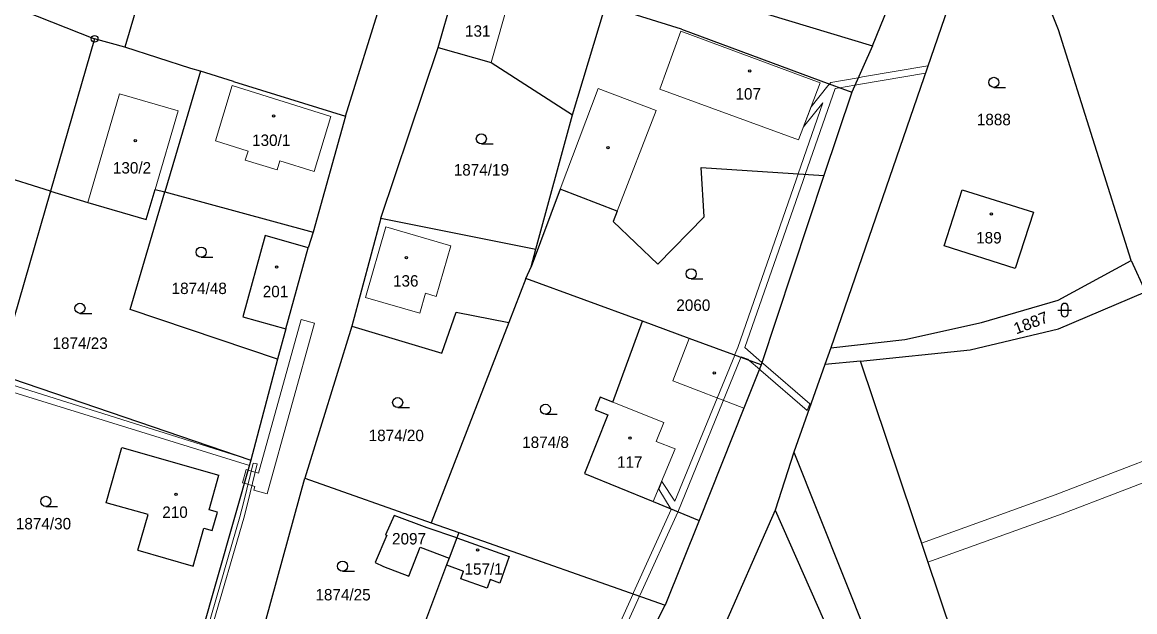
# Model space of a CAD drawing. Extents: x -820420 to -815896, y -1105820 to -1103643.
# Drawn here: x -818124.5 to -817959, y -1105443.7 to -1105356.1 of the extents above; entities that cross this region are included whole.
import ezdxf
from ezdxf.enums import TextEntityAlignment as Align

# ---------------------------------------------------------------- set-up
doc = ezdxf.new("R2010")
doc.units = 0
doc.header["$LTSCALE"] = 0.68
for name, color, linetype, lineweight in [('1', 7, 'Continuous', 25), ('13', 7, 'Continuous', 13), ('3', 7, 'Continuous', 25), ('4', 7, 'Continuous', 13), ('5', 7, 'Continuous', 25), ('8', 7, 'Continuous', 25)]:
    doc.layers.add(name, color=color, linetype=linetype, lineweight=lineweight)
doc.layers.add('2', color=7, linetype='Continuous')

msp = doc.modelspace()

# ---------------------------------------------------------------- linework, layer by layer
at = {"layer": '1'}
for p, q in [((-818102.39, -1105336.53), (-818109.27, -1105359.84)), ((-817970.34, -1105357.25), (-817977.63, -1105338.91)), ((-817982, -1105340.03), (-818004.22, -1105404.51)), ((-818076.41, -1105370.08), (-818069.32, -1105347.22)), ((-818062.64, -1105359.86), (-818059.62, -1105349.3)), ((-817998.02, -1105359.64), (-817994.74, -1105351.62)), ((-818124.41, -1105354.39), (-818113.75, -1105358.58)), ((-818042.65, -1105369.86), (-818037.9, -1105354.13)), ((-818026.42, -1105357.16), (-818034.57, -1105354.62)), ((-818013.64, -1105354.91), (-817998.02, -1105359.64)), ((-818026.42, -1105357.16), (-818005.71, -1105364.82)), ((-817959.52, -1105391.55), (-817970.34, -1105357.25)), ((-818113.75, -1105358.58), (-818120.31, -1105381.21)), ((-818109.27, -1105359.84), (-818113.75, -1105358.58)), ((-818099.42, -1105362.97), (-818109.27, -1105359.84)), ((-818071.19, -1105385.23), (-818062.64, -1105359.86)), ((-818062.64, -1105359.86), (-818054.77, -1105362.11)), ((-817998.02, -1105359.64), (-818001.1, -1105366.53)), ((-818054.77, -1105362.11), (-818042.65, -1105369.86)), ((-818098, -1105363.4), (-818099.88, -1105369.8)), ((-818098, -1105363.4), (-818099.42, -1105362.97)), ((-818093.1, -1105364.9), (-818098, -1105363.4)), ((-818093.1, -1105364.9), (-818076.41, -1105370.08)), ((-818005.71, -1105364.82), (-818001.1, -1105366.53)), ((-818001.1, -1105366.53), (-818005.25, -1105378.91)), ((-818099.88, -1105369.8), (-818103.3, -1105381.35)), ((-818076.41, -1105370.08), (-818081.24, -1105387.31)), ((-818048.09, -1105389.84), (-818042.65, -1105369.86)), ((-818120.31, -1105381.21), (-818129.72, -1105378.29)), ((-818023.51, -1105377.71), (-818005.25, -1105378.91)), ((-818023.06, -1105385.06), (-818023.51, -1105377.71)), ((-818005.25, -1105378.91), (-818014.59, -1105407.03)), ((-818120.31, -1105381.21), (-818128.21, -1105408.38)), ((-818120.31, -1105381.21), (-818114.77, -1105382.93)), ((-818108.46, -1105398.84), (-818103.3, -1105381.35)), ((-818106.07, -1105385.44), (-818104.72, -1105380.98)), ((-818104.72, -1105380.98), (-818103.3, -1105381.35)), ((-818103.3, -1105381.35), (-818081.24, -1105387.31)), ((-818044.47, -1105380.93), (-818048.81, -1105392.46)), ((-818036, -1105384.2), (-818044.47, -1105380.93)), ((-817987.33, -1105389.37), (-817984.69, -1105381.01)), ((-817984.69, -1105381.01), (-817974.04, -1105384.33)), ((-818114.77, -1105382.93), (-818106.07, -1105385.44)), ((-818036, -1105384.2), (-818036.59, -1105385.73)), ((-818071.19, -1105385.23), (-818075.5, -1105401.31)), ((-818071.19, -1105385.23), (-818048.09, -1105389.84)), ((-818036.59, -1105385.73), (-818029.95, -1105392.08)), ((-818029.95, -1105392.08), (-818023.06, -1105385.06)), ((-817974.04, -1105384.33), (-817976.78, -1105392.71)), ((-818081.24, -1105387.31), (-818081.98, -1105389.64)), ((-818088.36, -1105387.84), (-818091.72, -1105399.91)), ((-818081.98, -1105389.64), (-818088.36, -1105387.84)), ((-818085.32, -1105401.69), (-818081.98, -1105389.64)), ((-818048.81, -1105392.46), (-818048.09, -1105389.84)), ((-817976.78, -1105392.71), (-817987.33, -1105389.37)), ((-818049.58, -1105394.21), (-818048.81, -1105392.46)), ((-817970.41, -1105397.42), (-817959.52, -1105391.55)), ((-817959.52, -1105391.55), (-817957.4, -1105396.2)), ((-818049.58, -1105394.21), (-818052.13, -1105400.77)), ((-818032.25, -1105400.57), (-818049.58, -1105394.21)), ((-817981.82, -1105400.76), (-817970.41, -1105397.42)), ((-817970.34, -1105401.67), (-817957.4, -1105396.2)), ((-818086.54, -1105406.2), (-818108.46, -1105398.84)), ((-818091.72, -1105399.91), (-818085.32, -1105401.69)), ((-818052.13, -1105400.77), (-818063.69, -1105430.51)), ((-818062.07, -1105405.29), (-818059.98, -1105399.23)), ((-818059.98, -1105399.23), (-818052.13, -1105400.77)), ((-818036.66, -1105412.6), (-818032.25, -1105400.57)), ((-818025.31, -1105403.11), (-818032.25, -1105400.57)), ((-817993.22, -1105403.28), (-817981.82, -1105400.76)), ((-818085.32, -1105401.69), (-818086.54, -1105406.2)), ((-818075.5, -1105401.31), (-818082.49, -1105423.88)), ((-818075.5, -1105401.31), (-818062.07, -1105405.29)), ((-817983.48, -1105404.79), (-817970.34, -1105401.67)), ((-818014.59, -1105407.03), (-818025.31, -1105403.11)), ((-818004.22, -1105404.51), (-817993.22, -1105403.28)), ((-818004.22, -1105404.51), (-818005.1, -1105406.97)), ((-817999.82, -1105406.48), (-817983.48, -1105404.79)), ((-818086.54, -1105406.2), (-818090.49, -1105421.23)), ((-818014.59, -1105407.03), (-818017.16, -1105413.47)), ((-818005.1, -1105406.97), (-818009.73, -1105420.02)), ((-817999.82, -1105406.48), (-818005.1, -1105406.97)), ((-817981.08, -1105462.15), (-817999.82, -1105406.48)), ((-818128.21, -1105408.38), (-818090.49, -1105421.23)), ((-818038.53, -1105411.86), (-818039.28, -1105413.73)), ((-818036.66, -1105412.6), (-818038.53, -1105411.86)), ((-818039.28, -1105413.73), (-818037.4, -1105414.48)), ((-818017.16, -1105413.47), (-818023.81, -1105430.17)), ((-818037.4, -1105414.48), (-818040.86, -1105423.19)), ((-818112.05, -1105427.55), (-818109.69, -1105419.34)), ((-818109.69, -1105419.34), (-818095.28, -1105423.46)), ((-818009.73, -1105420.02), (-818012.52, -1105428.66)), ((-818009.73, -1105420.02), (-817994.18, -1105458.85)), ((-818090.49, -1105421.23), (-818099.7, -1105453.29)), ((-818096.73, -1105428.58), (-818095.28, -1105423.46)), ((-818088.22, -1105444.83), (-818082.49, -1105423.88)), ((-818082.49, -1105423.88), (-818063.69, -1105430.51)), ((-818040.86, -1105423.19), (-818030.63, -1105427.37)), ((-818105.78, -1105429.29), (-818112.05, -1105427.55)), ((-818095.46, -1105428.94), (-818096.73, -1105428.58)), ((-818030.63, -1105427.37), (-818023.81, -1105430.17)), ((-818012.52, -1105428.66), (-818024.71, -1105456.36)), ((-818012.52, -1105428.66), (-817998.06, -1105461.28)), ((-818107.3, -1105434.61), (-818105.78, -1105429.29)), ((-818096.24, -1105431.69), (-818095.46, -1105428.94)), ((-818069.16, -1105429.46), (-818070.49, -1105432.3)), ((-818064.28, -1105431.27), (-818069.16, -1105429.46)), ((-818063.69, -1105430.51), (-818059.58, -1105431.96)), ((-818023.81, -1105430.17), (-818028.84, -1105442.79)), ((-818099.11, -1105436.95), (-818097.51, -1105431.32)), ((-818097.51, -1105431.32), (-818096.24, -1105431.69)), ((-818059.88, -1105432.75), (-818064.28, -1105431.27)), ((-818059.58, -1105431.96), (-818059.88, -1105432.75)), ((-818059.58, -1105431.96), (-818028.84, -1105442.79)), ((-818070.26, -1105432.36), (-818072.03, -1105436.41)), ((-818070.49, -1105432.3), (-818070.26, -1105432.36)), ((-818059.88, -1105432.75), (-818061.01, -1105435.77)), ((-818059.88, -1105432.75), (-818052.05, -1105435.56)), ((-818107.3, -1105434.61), (-818099.11, -1105436.95)), ((-818067, -1105438.45), (-818065.32, -1105434.15)), ((-818065.32, -1105434.15), (-818061.01, -1105435.77)), ((-818072.03, -1105436.41), (-818070.79, -1105437.03)), ((-818070.79, -1105437.03), (-818067, -1105438.45)), ((-818061.39, -1105436.77), (-818067.26, -1105452.42)), ((-818061.01, -1105435.77), (-818061.39, -1105436.77)), ((-818061.39, -1105436.77), (-818058.88, -1105437.71)), ((-818052.05, -1105435.56), (-818053.46, -1105439.5)), ((-818059.28, -1105438.85), (-818058.88, -1105437.71)), ((-818055.37, -1105440.24), (-818059.28, -1105438.85)), ((-818054.92, -1105438.98), (-818055.37, -1105440.24)), ((-818053.46, -1105439.5), (-818054.92, -1105438.98)), ((-818039.13, -1105462.6), (-818028.84, -1105442.79))]:
    msp.add_line(p, q, dxfattribs=at)
at = {"layer": '13'}
for points in [[(-817989.77, -1105362.59), (-817999.5, -1105364.25), (-818000.13, -1105364.36), (-818000.62, -1105365.46), (-817999.81, -1105365.32), (-817990.15, -1105363.67)], [(-818000.13, -1105364.36), (-818004.22, -1105365.06), (-818004.42, -1105365.3), (-818002.93, -1105365.85), (-818000.62, -1105365.46)], [(-818002.93, -1105365.85), (-818004.42, -1105365.3), (-818004.65, -1105365.58), (-818007.12, -1105368.67), (-818008.26, -1105371.68), (-818005.38, -1105368.1), (-818009.06, -1105378.66), (-818009.37, -1105379.55), (-818018.05, -1105404.46), (-818018.49, -1105405.52), (-818018.52, -1105405.59), (-818017.58, -1105405.94), (-818017.54, -1105405.85), (-818016.57, -1105406.2), (-818016.36, -1105406.38), (-818014.59, -1105407.03), (-818014.48, -1105406.69), (-818017.01, -1105404.49), (-818008.33, -1105379.64), (-818008.01, -1105378.73), (-818003.56, -1105365.96)], [(-817906.26, -1105403.62), (-817870.42, -1105388.81), (-817857.72, -1105384.7), (-817855.6, -1105384.19), (-817850.44, -1105382.95), (-817847.44, -1105379.56), (-817849.48, -1105379.64), (-817852.45, -1105380.35), (-817858.54, -1105381.8), (-817871.44, -1105385.99), (-817907.52, -1105400.9), (-817913.62, -1105403.79), (-817946.01, -1105416.87), (-817970.85, -1105426.37), (-817990.71, -1105433.53), (-817989.76, -1105436.38), (-817969.79, -1105429.17), (-817944.93, -1105419.67), (-817912.4, -1105406.53)], [(-818083.03, -1105400.29), (-818089.38, -1105423.14), (-818090.91, -1105422.69), (-818091.47, -1105424.65), (-818089.92, -1105425.11), (-818090.07, -1105425.69), (-818088.09, -1105426.23), (-818081.05, -1105400.85)], [(-818032.68, -1105441.44), (-818032.59, -1105441.25), (-818027, -1105428.93), (-818017.58, -1105405.94), (-818018.52, -1105405.59), (-818027.44, -1105427.33), (-818029.34, -1105424.4), (-818029.81, -1105425.51), (-818027.95, -1105428.53), (-818033.55, -1105440.91), (-818033.64, -1105441.1)], [(-818016.36, -1105406.38), (-818014.85, -1105407.69), (-818014.59, -1105407.03)], [(-818014.48, -1105406.69), (-818014.59, -1105407.03), (-818014.85, -1105407.69), (-818014.62, -1105407.89), (-818007.75, -1105413.84), (-818007.36, -1105412.86), (-818014.23, -1105406.9)], [(-818128.53, -1105409.59), (-818128.79, -1105410.57), (-818127.23, -1105410.7), (-818090.71, -1105422), (-818090.49, -1105421.23), (-818127.03, -1105409.72)], [(-818109.75, -1105451.26), (-818104.73, -1105452.62), (-818100.81, -1105453.75), (-818099.35, -1105453.87), (-818098.43, -1105453.95), (-818097.44, -1105449.94), (-818096.34, -1105446.27), (-818091.57, -1105429.82), (-818090.96, -1105427.51), (-818089.57, -1105421.78), (-818090.15, -1105421.64), (-818091.54, -1105427.37), (-818092.15, -1105429.66), (-818096.92, -1105446.11), (-818098.02, -1105449.78), (-818098.89, -1105453.31), (-818099.7, -1105453.29), (-818100.71, -1105453.15), (-818104.57, -1105452.04), (-818110.17, -1105450.52), (-818110.59, -1105452.01), (-818110.04, -1105452.16)], [(-818090.91, -1105422.69), (-818091.2, -1105422.61), (-818091.76, -1105424.57), (-818091.47, -1105424.65)], [(-818033.64, -1105441.1), (-818040.78, -1105456.89), (-818041.21, -1105457.9), (-818042.59, -1105461.25), (-818042.62, -1105461.34), (-818041.68, -1105461.68), (-818041.64, -1105461.58), (-818039.78, -1105457.1), (-818032.68, -1105441.44)]]:
    msp.add_lwpolyline(points, close=True, dxfattribs=at)
at = {"layer": '3'}
for p, q in [((-817979.953, -1105365.8), (-817978.203, -1105365.8)), ((-818056.213, -1105374.19), (-818054.463, -1105374.19)), ((-818097.893, -1105391.05), (-818096.143, -1105391.05)), ((-818025.003, -1105394.27), (-818023.253, -1105394.27)), ((-817970.421, -1105398.911), (-817968.419, -1105398.911)), ((-817969.921, -1105398.411), (-817969.921, -1105399.412)), ((-817968.919, -1105399.412), (-817968.919, -1105398.411)), ((-818115.933, -1105399.39), (-818114.183, -1105399.39)), ((-818068.663, -1105413.41), (-818066.913, -1105413.41)), ((-818046.683, -1105414.4), (-818044.933, -1105414.4)), ((-818121.013, -1105428.09), (-818119.263, -1105428.09)), ((-818076.853, -1105437.72), (-818075.103, -1105437.72))]:
    msp.add_line(p, q, dxfattribs=at)
for centre in [(-817979.9529, -1105365.0498), (-818056.2129, -1105373.4398), (-818097.8929, -1105390.2998), (-818025.0029, -1105393.5198), (-818115.9329, -1105398.6398), (-818068.6629, -1105412.6598), (-818046.6829, -1105413.6498), (-818121.0129, -1105427.3398), (-818076.8529, -1105436.9698)]:
    msp.add_circle(centre, 0.75, dxfattribs=at)
for centre, start, end in [((-817969.42, -1105398.4109), 0, 180), ((-817969.42, -1105399.4109), 180, 359.98789)]:
    msp.add_arc(centre, 0.5, start, end, dxfattribs=at)
at = {"layer": '4'}
for p, q in [((-818054.77, -1105362.11), (-818051.75, -1105351.55)), ((-818029.68, -1105366.08), (-818026.52, -1105357.44)), ((-818005.82, -1105365.1), (-818026.52, -1105357.44)), ((-818093.29, -1105365.53), (-818095.77, -1105373.76)), ((-818078.59, -1105370.11), (-818093.29, -1105365.53)), ((-818044.47, -1105380.93), (-818038.84, -1105365.96)), ((-818030.22, -1105369.22), (-818038.84, -1105365.96)), ((-818005.82, -1105365.1), (-818009.04, -1105373.59)), ((-818114.77, -1105382.93), (-818110.05, -1105366.77)), ((-818110.05, -1105366.77), (-818101.31, -1105369.3)), ((-818009.04, -1105373.59), (-818029.68, -1105366.08)), ((-818101.31, -1105369.3), (-818104.72, -1105380.98)), ((-818036, -1105384.2), (-818030.22, -1105369.22)), ((-818081.07, -1105378.31), (-818078.59, -1105370.11)), ((-818095.77, -1105373.76), (-818090.92, -1105375.26)), ((-818091.34, -1105376.62), (-818090.92, -1105375.26)), ((-818091.34, -1105376.62), (-818086.6, -1105378.07)), ((-818086.6, -1105378.07), (-818086.18, -1105376.73)), ((-818086.18, -1105376.73), (-818081.07, -1105378.31)), ((-818070.43, -1105386.54), (-818073.45, -1105397.04)), ((-818070.43, -1105386.54), (-818060.74, -1105389.33)), ((-818060.74, -1105389.33), (-818062.91, -1105396.87)), ((-818073.45, -1105397.04), (-818065.38, -1105399.36)), ((-818064.53, -1105396.4), (-818065.38, -1105399.36)), ((-818062.91, -1105396.87), (-818064.53, -1105396.4)), ((-818025.31, -1105403.11), (-818027.73, -1105409.41)), ((-818027.73, -1105409.41), (-818017.16, -1105413.47)), ((-818029.07, -1105415.62), (-818036.66, -1105412.6)), ((-818030.19, -1105418.43), (-818029.07, -1105415.62)), ((-818027.38, -1105419.55), (-818030.19, -1105418.43)), ((-818030.63, -1105427.37), (-818027.38, -1105419.55))]:
    msp.add_line(p, q, dxfattribs=at)
at = {"layer": '5'}
for centre in [(-818016.2868, -1105363.3492), (-818087.1168, -1105370.0492), (-818107.7068, -1105373.7192), (-818037.3768, -1105374.7792), (-817980.3168, -1105384.6192), (-818086.6668, -1105392.5092), (-818067.3668, -1105391.1192), (-818021.5568, -1105408.2492), (-818034.1168, -1105417.9292), (-818101.6268, -1105426.2992), (-818056.7768, -1105434.5592)]:
    msp.add_circle(centre, 0.175, dxfattribs=at)
at = {"layer": '8'}
for radius in [0.5, 0.0303]:
    msp.add_circle((-818113.75, -1105358.5799), radius, dxfattribs=at)

# ---------------------------------------------------------------- texts
at = {"layer": '2'}
for s, p in [('131', (-818056.749, -1105358.265)), ('107', (-818016.509, -1105367.615)), ('1888', (-817979.96, -1105371.425)), ('130/1', (-818087.48, -1105374.505)), ('130/2', (-818108.19, -1105378.605)), ('1874/19', (-818056.209, -1105378.905)), ('189', (-817980.699, -1105389.005)), ('136', (-818067.459, -1105395.415)), ('1874/48', (-818098.189, -1105396.525)), ('201', (-818086.839, -1105396.995)), ('2060', (-818024.67, -1105399.025)), ('1874/23', (-818115.909, -1105404.675)), ('1874/20', (-818068.869, -1105418.385)), ('1874/8', (-818046.66, -1105419.405)), ('117', (-818034.129, -1105422.345)), ('210', (-818101.789, -1105429.795)), ('1874/30', (-818121.359, -1105431.505)), ('2097', (-818066.97, -1105433.745)), ('157/1', (-818055.87, -1105438.245)), ('1874/25', (-818076.789, -1105442.065))]:
    msp.add_text(s, height=1.7, dxfattribs=at).set_placement(p, align=Align.CENTER)
at = {"layer": '2', "width": 1.05}
msp.add_text('1887', height=1.7, rotation=21, dxfattribs=at).set_placement((-817974.1521, -1105401.5869), align=Align.CENTER)

doc.saveas('drawing.dxf')
